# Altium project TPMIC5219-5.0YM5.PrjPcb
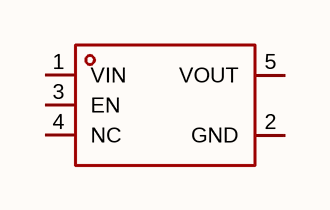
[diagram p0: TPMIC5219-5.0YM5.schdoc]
1 sheet, 1 parts. Net scope: global (net labels, ports and power ports of the same name join across sheets).

## Sheet TPMIC5219-5.0YM5.schdoc
size 127 x 101 mm

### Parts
U?  tpmic5219-5.0ym5  [SOT-23-5_L3.0-W1.6-P0.95-LS2.8-BR]  (value not drawn)

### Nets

Not connected (* = marked no-connect by the designer): U? 1(VIN) 2(GND) 3(EN) 4(NC) 5(VOUT)

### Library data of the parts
U? = tpmic5219-5.0ym5: 输出极性:正极;工作电压:20V;输出电压:5V;输出电流:500mA;电源纹波抑制比(PSRR):70dB@(1kHz);输出类型:固定;; Manufacturer: TECH PUBLIC(台舟); AddInBom: yes; ModelId: 72410e292833493f86746b22636ce101; ModelTransform: 110.236,116.1415,0,0,0,0,0.002,0.001,0; Output Configuration: 正极; Voltage - Supply: 20V; Output Voltage: 5V; Output Current: 500mA; Voltage Dropout: 350mV@(100mA); standby current: 1.5uA; Output Type: 固定; Number of Outputs: 1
